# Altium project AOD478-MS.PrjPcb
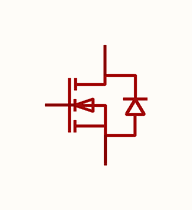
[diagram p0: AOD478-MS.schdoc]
1 sheet, 1 parts. Net scope: global (net labels, ports and power ports of the same name join across sheets).

## Sheet AOD478-MS.schdoc
size 127 x 101 mm

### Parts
Q?  aod478-ms  [TO-252-3_L6.6-W6.1-P4.57-LS9.9-BR-CW]  (value not drawn)

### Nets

Not connected (* = marked no-connect by the designer): Q? 1(G) 2(D) 3(S)

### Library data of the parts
Q? = aod478-ms: 数量:1个N沟道;漏源电压(Vdss):100V;连续漏极电流(Id):20A;导通电阻(RDS(on)):70mΩ@10V;耗散功率(Pd):34.7W;阈值电压(Vgs(th)):2.5V;; Manufacturer: MSKSEMI(美森科); AddInBom: yes; ModelId: dee852f3c6b348a2b9d5be5dd3244081; ModelTransform: 258.97184,390.1567,0,90,0,0,-35.433,0,0; Number: 1个N沟道; Drain to Source Voltage: 100V; Current - Continuous Drain(Id): 20A; Pd - Power Dissipation: 34.7W; Gate Threshold Voltage (Vgs(th)): 2.5V; Gate Charge(Qg): 26.2nC@10V; Input Capacitance(Ciss): 1.535nF; Reverse Transfer Capacitance (Crss@Vds): 37pF; Type: N沟道; Output Capacitance(Coss): 60pF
